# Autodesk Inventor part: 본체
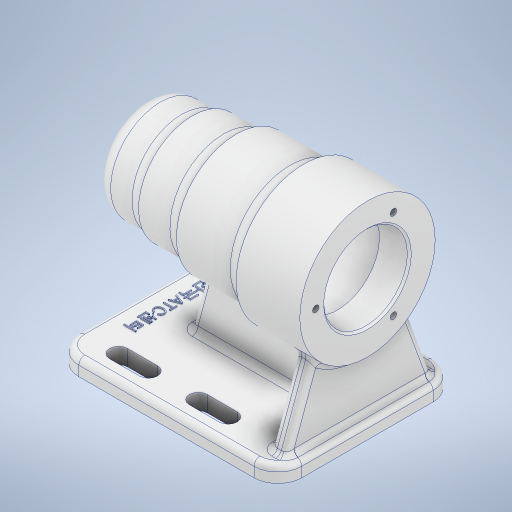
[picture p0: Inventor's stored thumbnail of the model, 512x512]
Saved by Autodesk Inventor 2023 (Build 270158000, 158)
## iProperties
Created: 2022-07
Part Number: 본체
Material: 알루미늄 6061
Document SubType Name: Modeling
Designer: owner
Density: 2.7 g/cm^3
Appearance: 알루미늄 - 평지
Mass: 702.592 g
Surface Area: 702.258 cm^2
Volume: 260.219 cm^3
Author: owner
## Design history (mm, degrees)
sketch "스케치1"
  geometry: L1 (-56, 0)-(56, 0); L2 (-56, 0)-(-56, 17); L3 (-48, 25)-(-32, 25); L4 (-32, 25)-(-32, 27); L5 (-32, 27)-(-10, 27); L6 (-10, 27)-(-10, 30); L7 (-10, 30)-(24, 30); L8 (24, 30)-(24, 34); L9 (24, 34)-(56, 34); L10 (56, 34)-(56, 0); A1 r 8 centre (-48, 17) between (-48, 25) and (-56, 17); 3 further points
  constraints: 20 end point, 8 perpendicular, 2 point on circle, 2 point on line, 2 tangent, 1 centre point, 1 coincident, 1 horizontal, 1 midpoint, 1 vertical
  dimensions: "d1" = 25 distance of L1.start point (-56, 25); "d2" = 24 distance of point (-56, 25) L3.end; "d3" = 2 distance of L3.end L4.end; "d4" = 22 distance of L4.end L5.end; "d5" = 3 distance of L5.end L6.end; "d6" = 34 distance of L6.end L7.end; "d7" = 4 distance of L7.end L8.end; "d8" = 32 distance of L8.end L9.end; "d9" = 8 radius of A1
revolve "회전1" sketch "스케치1" stored, may be unused: angle "d10" = 90 deg
fillet "모깎기1" dims "d11" = 8
sketch "스케치2"
  geometry: L1 (-56, -17)-(-56, 17) reference; L2 (-56, 0)-(56, 0); L3 (56, -34)-(56, 34) reference; L4 (56, 0)-(56, 21); L5 (56, 21)-(41, 21); L6 (41, 21)-(41, 24); L7 (41, 24)-(-10, 24); L8 (-13, 21)-(-13, 21); L9 (-13, 21)-(-24.7, 21); L10 (-25, 20.7)-(-25, 17.5); L11 (-25, 17.5)-(-42.7, 17.5); L12 (-37.292, -25)-(-37.292, 25) reference; L13 (-43, 17.2)-(-43, 16); L14 (-43, 16)-(-46.7, 16); L15 (-48, -25)-(-48, 25) reference; L16 (-47, 15.7)-(-47, 10.5); L17 (-47, 10.5)-(-47, 10.5); L18 (-50, 7.5)-(-50, 0); A1 r 0.3 centre (-46.7, 15.7) between (-46.7, 16) and (-47, 15.7); A2 r 0.3 centre (-42.7, 17.2) between (-42.7, 17.5) and (-43, 17.2); A3 r 0.3 centre (-24.7, 20.7) between (-24.7, 21) and (-25, 20.7); A4 r 3 centre (-47, 7.5) between (-47, 10.5) and (-50, 7.5); A5 r 3 centre (-10, 21) between (-10, 24) and (-13, 21); 5 further points
  constraints: 28 end point, 10 perpendicular, 10 point on circle, 10 tangent, 8 point on line, 5 centre point, 2 equal radius, 2 midpoint, 1 horizontal
  dimensions: "d12" = 42 diameter of L5 L2; "d13" = 48 diameter of L7 L2; "d14" = 15 distance between parallel lines of L3 L6; "d15" = 54 distance between parallel lines of L8 L6; "d16" = 18 distance of L10.end point (-43, 17.5); "d17" = 12 distance of L8.end point (-25, 21); "d18" = 35 diameter of L11 L2; "d19" = 32 diameter of L14 L2; "d20" = 21 diameter of L17 L2; "d21" = 3 distance between parallel lines of L16 L18; "d22" = 4 distance between parallel lines of L13 L16; "d23" = 0.3 radius of A1 (derived); "d24" = 3 radius of A4; "d25" = 3 radius of A5 (derived)
revolve "회전2" sketch "스케치2" stored, may be unused: angle "d26" = 90 deg
chamfer "모따기1" distance "d27" = 1; stored, may be unused: second distance "d28" = 2, angle "d29" = 45 deg
sketch "스케치3" dims "d37" = 52
  geometry: 5 further points
  constraints: 1 coincident, 1 horizontal alignment, 7 other
  dimensions: "d40" = 360 deg dimension on point (0, 0) point (13, 22.517) (derived)
hole "구멍1" sketch "스케치3" at (13, 22.517), (-26, 0), (13, -22.517) diameter "d30" = 3.242; stored, may be unused: countersink angle "d34" = 90 deg, drill point angle "d36" = 118 deg; dims "d31" = 8, "d32" = 4, "d33" = 2, "d35" = 11
node "작업 평면1"
sketch "스케치4"
  geometry: L1 (-44, 45)-(44, 45); L2 (56, 33)-(56, -33); L3 (44, -45)-(-44, -45); L4 (-56, -33)-(-56, 33); L5 (-56, 45)-(56, -45); L6 (56, 45)-(-56, -45); A1 r 12 centre (44, -33) between (44, -45) and (56, -33); A2 r 12 centre (-44, -33) between (-56, -33) and (-44, -45); A3 r 12 centre (-44, 33) between (-44, 45) and (-56, 33); A4 r 12 centre (44, 33) between (56, 33) and (44, 45); 1 further point
  constraints: 12 end point, 8 point on circle, 8 point on line, 8 tangent, 4 centre point, 3 equal radius, 2 midpoint, 2 parallel, 1 horizontal, 1 perpendicular
  dimensions: "d43" = 90 distance of L6.start L5.end; "d44" = 112 distance of L5.end L6.end; "d45" = 12 radius of A1
extrude "돌출1" join sketch "스케치4" distance "d46" = 8; taper "d47" = 0 deg
fillet "모깎기2" dims "d48" = 3
sketch "스케치5"
  geometry: L1 (-36, 33)-(-21, 33); L2 (-36, 28.5)-(-21, 28.5); L3 (-21, 37.5)-(-36, 37.5); L4 (4, 33)-(19, 33); L5 (4, 28.5)-(19, 28.5); L6 (19, 37.5)-(4, 37.5); L7 (-56, 33)-(-56, -33) reference; L8 (-56, 33)-(-56, -33) reference; L9 (-56, 0)-(56, 0); L10 (56, -33)-(56, 33) reference; L11 (-21, -37.5)-(-36, -37.5); L12 (-36, -28.5)-(-21, -28.5); L13 (19, -37.5)-(4, -37.5); L14 (4, -28.5)-(19, -28.5); A1 r 4.5 centre (-36, 33) between (-36, 37.5) and (-36, 28.5); A2 r 4.5 centre (-21, 33) between (-21, 28.5) and (-21, 37.5); A3 r 4.5 centre (4, 33) between (4, 37.5) and (4, 28.5); A4 r 4.5 centre (19, 33) between (19, 28.5) and (19, 37.5); A5 r 4.5 centre (-36, -33) between (-36, -28.5) and (-36, -37.5); A6 r 4.5 centre (-21, -33) between (-21, -37.5) and (-21, -28.5); A7 r 4.5 centre (4, -33) between (4, -28.5) and (4, -37.5); A8 r 4.5 centre (19, -33) between (19, -37.5) and (19, -28.5); 3 further points
  constraints: 26 end point, 16 point on circle, 12 symmetric about line, 8 centre point, 8 tangent, 4 midpoint, 2 parallel, 2 point on line, 1 horizontal, 1 horizontal alignment, 4 other
  dimensions: "d49" = 15 distance of L1.start L1.end; "d50" = 9 diameter of A2; "d51" = 15 distance of L4.start L4.end; "d52" = 9 diameter of A4; "d57" = 20 distance from line of L7 L1.start; "d58" = 25 distance of L4.start L1.end; "d62" = 66 diameter of L1.start L9
extrude "돌출2" cut sketch "스케치5" extent not by distance; stored distance "d63" = 0; taper "d64" = 0 deg
sketch "스케치8"
  geometry: L1 (-44, -62)-(44, -62) reference; L2 (-29, -62)-(-19.232, -25.544); L3 (-29, -62)-(8.742, -62); L4 (-19.232, -25.544)-(48, -25.544); L5 (56, -34)-(56, 34) reference; L6 (48, -25.544)-(48, -62); L7 (56, -70)-(56, -65) reference; L8 (44, -70)-(-44, -70) reference; L9 (-29, -62)-(48, -62); 2 further points
  constraints: 10 end point, 1 collinear, 1 equal length, 1 horizontal, 1 perpendicular, 1 point on line, 1 vertical
  dimensions: "d77" = 75 deg angle of L3 L2; "d79" = 8 distance between parallel lines of L7 L6; "d80" = 77 distance from line of L2.start L6; "d81" = 44.45645 distance between parallel lines of L8 L4
extrude "돌출3" join sketch "스케치8" stored distance "d82" = 8; taper "d83" = 0 deg
sketch "스케치9"
  geometry: L1 (-33.5, 0)-(-24.5, 0) reference; L2 (-33, 0)-(-19.075, 38.257); L3 (-33, 0)-(7.713, 0); L4 (-19.075, 38.257)-(27.075, 38.257); L5 (27.075, 38.257)-(41, 0); L6 (37, 0)-(46, 0) reference; L7 (27.075, 38.257)-(67.788, 38.257); L8 (-41, -8)-(-41, -3) reference; L9 (49, -8)-(49, -3) reference; L10 (37, -8)-(-29, -8) reference; L11 (-29, 0)-(37, 0) reference; L12 (32.5, 0)-(41.5, 0) reference; 1 further point
  constraints: 10 end point, 2 equal length, 2 horizontal, 2 point on line, 1 parallel
  dimensions: "d84" = 70 deg angle of L3 L2; "d85" = 70 deg angle of L5 L7; "d86" = 8 distance from line of L8 L2.start; "d87" = 8 distance from line of L9 L5.end; "d89" = 46.25738 distance between parallel lines of L10 L4
extrude "돌출4" join sketch "스케치9" stored distance "d90" = 8; taper "d91" = 0 deg
fillet "모깎기3" dims "d92" = 3
fillet "모깎기4" dims "d93" = 3
fillet "모깎기5" dims "d94" = 3
fillet "모깎기6" dims "d95" = 3
fillet "모깎기7" dims "d96" = 3
fillet "모깎기8" dims "d97" = 3
sketch "스케치10"
  geometry: L1 (-56, 33)-(-56, -33) reference; 2 further points
  constraints: 1 horizontal alignment, 1 other
  dimensions: "d98" = 12 distance from line of L1 point (-44, 0)
feature "엠보싱1" sketch "스케치10" dims "d1" = 25, "d2" = 24, "d3" = 2, "d4" = 22, "d5" = 3, "d6" = 34, "d7" = 4, "d8" = 32, "d9" = 8, "d12" = 42, "d13" = 48, "d14" = 15, "d15" = 54, "d16" = 18, "d17" = 12, "d18" = 35, "d19" = 32, "d20" = 21, "d21" = 3, "d22" = 4, "d23" = 0.3 (derived), "d24" = 3, "d25" = 3 (derived), "d99" = 0.5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
node "솔리드1"
feature "A9D066F2-1C7D-4E18-AEED-F7BC21143FA4" dims "d30" = 3.242, "d31" = 8, "d32" = 4, "d33" = 2, "d34" = 90 deg, "d35" = 11, "d36" = 118 deg
